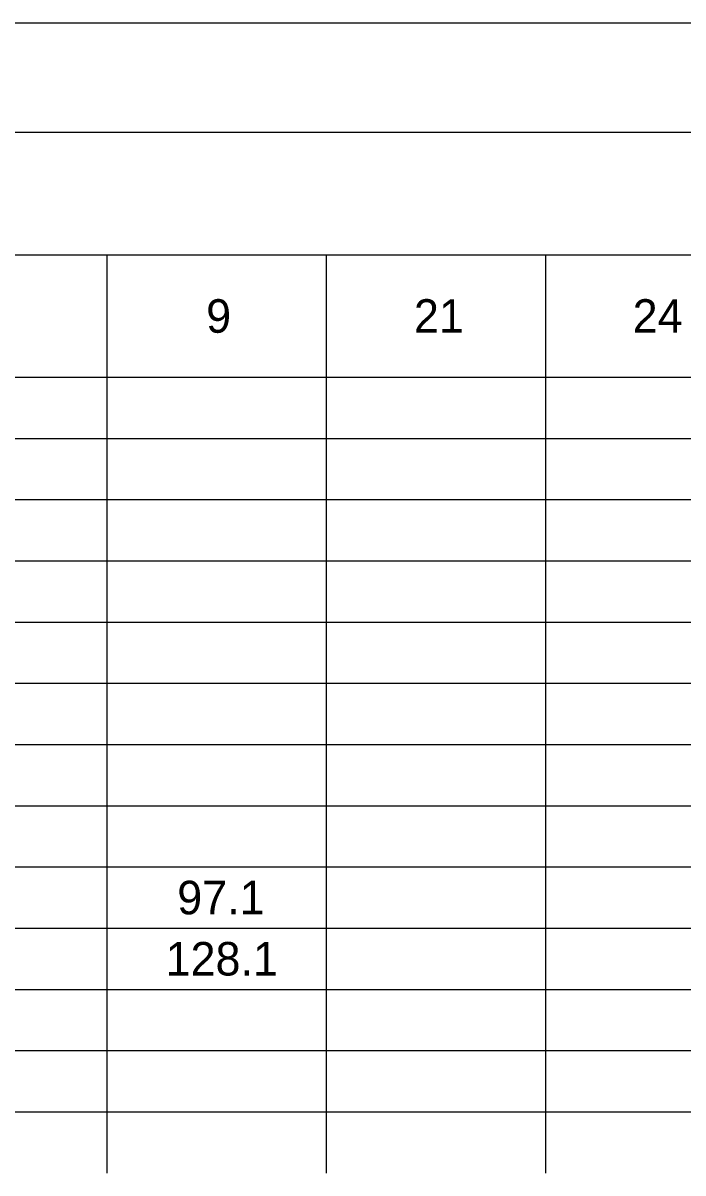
# Model space of a CAD drawing. Extents: x 0 to 34, y 0 to 22.
# Drawn here: x 3.12 to 6.14, y 16.74 to 22 of the extents above; entities that cross this region are included whole.
import ezdxf

# ---------------------------------------------------------------- set-up
doc = ezdxf.new("R2010")
doc.units = 0
for name, color, linetype in [('Default', 7, 'Continuous'), ('SH_Border', 7, 'Continuous'), ('SH_Cut_Line', 7, 'Continuous')]:
    doc.layers.add(name, color=color, linetype=linetype)

msp = doc.modelspace()

# ---------------------------------------------------------------- linework, layer by layer
at = {"layer": 'Default'}
for p, q in [((1.5, 21.5), (6.5126, 21.5)), ((1.5, 20.94), (6.5126, 20.94)), ((3.5051, 20.94), (3.5051, 20.66)), ((4.5076, 20.94), (4.5076, 20.66)), ((5.5101, 20.94), (5.5101, 20.66)), ((3.5051, 20.66), (3.5051, 20.38)), ((4.5076, 20.66), (4.5076, 20.38)), ((5.5101, 20.66), (5.5101, 20.38)), ((1.5, 20.38), (6.5126, 20.38)), ((3.5051, 20.38), (3.5051, 20.1)), ((4.5076, 20.38), (4.5076, 20.1)), ((5.5101, 20.38), (5.5101, 20.1)), ((1.5, 20.1), (6.5126, 20.1)), ((3.5051, 20.1), (3.5051, 18.7)), ((4.5076, 20.1), (4.5076, 18.7)), ((5.5101, 20.1), (5.5101, 18.7)), ((1.5, 19.82), (6.5126, 19.82)), ((1.5, 19.54), (6.5126, 19.54)), ((1.5, 19.26), (6.5126, 19.26)), ((1.5, 18.98), (6.5126, 18.98)), ((1.5, 18.7), (6.5126, 18.7)), ((3.5051, 18.7), (3.5051, 18.14)), ((4.5076, 18.7), (4.5076, 18.14)), ((5.5101, 18.7), (5.5101, 18.14)), ((1.5, 18.42), (6.5126, 18.42)), ((1.5, 18.14), (6.5126, 18.14)), ((3.5051, 18.14), (3.5051, 17.86)), ((4.5076, 18.14), (4.5076, 17.86)), ((5.5101, 18.14), (5.5101, 17.86)), ((1.5, 17.86), (6.5126, 17.86)), ((3.5051, 17.86), (3.5051, 17.58)), ((4.5076, 17.86), (4.5076, 17.58)), ((5.5101, 17.86), (5.5101, 17.58)), ((1.5, 17.58), (6.5126, 17.58)), ((3.5051, 17.58), (3.5051, 17.3)), ((4.5076, 17.58), (4.5076, 17.3)), ((5.5101, 17.58), (5.5101, 17.3)), ((1.5, 17.3), (6.5126, 17.3)), ((3.5051, 17.3), (3.5051, 17.02)), ((4.5076, 17.3), (4.5076, 17.02)), ((5.5101, 17.3), (5.5101, 17.02)), ((1.5, 17.02), (6.5126, 17.02)), ((3.5051, 17.02), (3.5051, 16.74)), ((4.5076, 17.02), (4.5076, 16.74)), ((5.5101, 17.02), (5.5101, 16.74))]:
    msp.add_line(p, q, dxfattribs=at)
at = {"layer": 'SH_Border'}
msp.add_lwpolyline([(1.5, 21.5), (33.5, 21.5), (33.5, 0.5), (1.5, 0.5)], close=True, dxfattribs=at)
at = {"layer": 'SH_Cut_Line'}
msp.add_lwpolyline([(0, 0), (34, 0), (34, 22), (0, 22)], close=True, dxfattribs=at)

# ---------------------------------------------------------------- texts
at = {"layer": 'Default'}
for s, height, p in [('9', 0.1533, (3.9585, 20.5833)), ('21', 0.15333, (4.9084, 20.5833)), ('24', 0.15333, (5.9082, 20.5833)), ('97.1', 0.15333, (3.8263, 17.9233)), ('128.1', 0.15333, (3.7732, 17.6433))]:
    msp.add_text(s, height=height, dxfattribs=at).set_placement(p)

doc.saveas('drawing.dxf')
